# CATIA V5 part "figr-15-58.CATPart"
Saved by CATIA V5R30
Part number: Part1
Bounding box of the stored display mesh (mm): x -20 to 20, y -25 to 25, z 0 to 50
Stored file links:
  D:\PROJECTS\CATIA V56R 2020\Resources\Parts File\c15_catia_v5_6r2020_prt\figr-15-58.CATPart
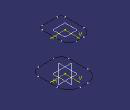
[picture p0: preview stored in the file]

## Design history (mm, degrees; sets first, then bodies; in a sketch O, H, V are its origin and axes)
SheetMetalParameters1: Thickness 2, BendRadius 4, KFactor 0.400515 {= log(min(100,max(20*SheetMetalParameters1.BendRadius,SheetMetalParameters1.Thickness)/SheetMetalParameters1.Thickness))/log(100)/2}, ReliefRadialLength 1, ReliefAxialLength 2, MinimumBendRadius 0
Body1 (main body)
  Plane1: type Offset, RefPlane xy-plane, Offset 50
  Sketch1 on xy-plane, origin (0, 0, 0), H (1, 0, 0), V (0, 1, 0)
    line L1 (20, 10) -> (20, -15)
    line L2 (10, -25) -> (-10, -25)
    line L3 (-20, -15) -> (-20, 10)
    line L4 (-5, 25) -> (5, 25)
    arc A1 centre (5, 10) radius 15 from (20, 10) to (5, 25) ccw
    arc A2 centre (-5, 10) radius 15 from (-20, 10) to (-5, 25) cw
    arc A3 centre (10, -15) radius 10 from (20, -15) to (10, -25) cw
    arc A4 centre (-10, -15) radius 10 from (-10, -25) to (-20, -15) cw
    radius A1 = 15
    radius A2 = 15
    radius A3 = 10
    radius A4 = 10
    distance L4 L2 = 50
    distance L3 L1 = 40
    vertical: L1 V, L3 V
    horizontal: L2 H, L4 H
    equidistance: L1 L3 O, L2 L4 O
    tangency: A1 L1, A1 L4, A2 L3, A2 L4, A3 L1, A3 L2, A4 L2, A4 L3
  Sketch2 on Plane1, origin (0, 0, 50), H (1, 0, 0), V (0, 1, 0)
    line L1 (15, 10) -> (15, -15)
    line L2 (10, -20) -> (-10, -20)
    line L3 (-15, -15) -> (-15, 10)
    line L4 (-5, 20) -> (5, 20)
    arc A1 centre (5, 10) radius 10 from (15, 10) to (5, 20) ccw
    arc A2 centre (10, -15) radius 5 from (15, -15) to (10, -20) cw
    arc A3 centre (-10, -15) radius 5 from (-10, -20) to (-15, -15) cw
    arc A4 centre (-5, 10) radius 10 from (-15, 10) to (-5, 20) cw
    radius A1 = 10
    radius A2 = 5
    radius A3 = 5
    radius A4 = 10
    distance L4 L2 = 40
    distance L1 L3 = 30
    vertical: L1 V, L3 V
    horizontal: L2 H, L4 H
    equidistance: L1 L3 O, L2 L4 O
    tangency: A1 L1, A1 L4, A2 L1, A2 L2, A3 L2, A3 L3, A4 L3, A4 L4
